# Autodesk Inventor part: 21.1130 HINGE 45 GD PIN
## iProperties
Created: 2007-01
Part Number: 21.1130 HINGE 45 GD PIN
Document SubType Name: Modeling
Designer: Andy Moles
Material: Steel
Density: 7.85 g/cm^3
Author: Andy Moles
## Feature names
1. Extrusion1
2. Chamfer1
3. Chamfer2
